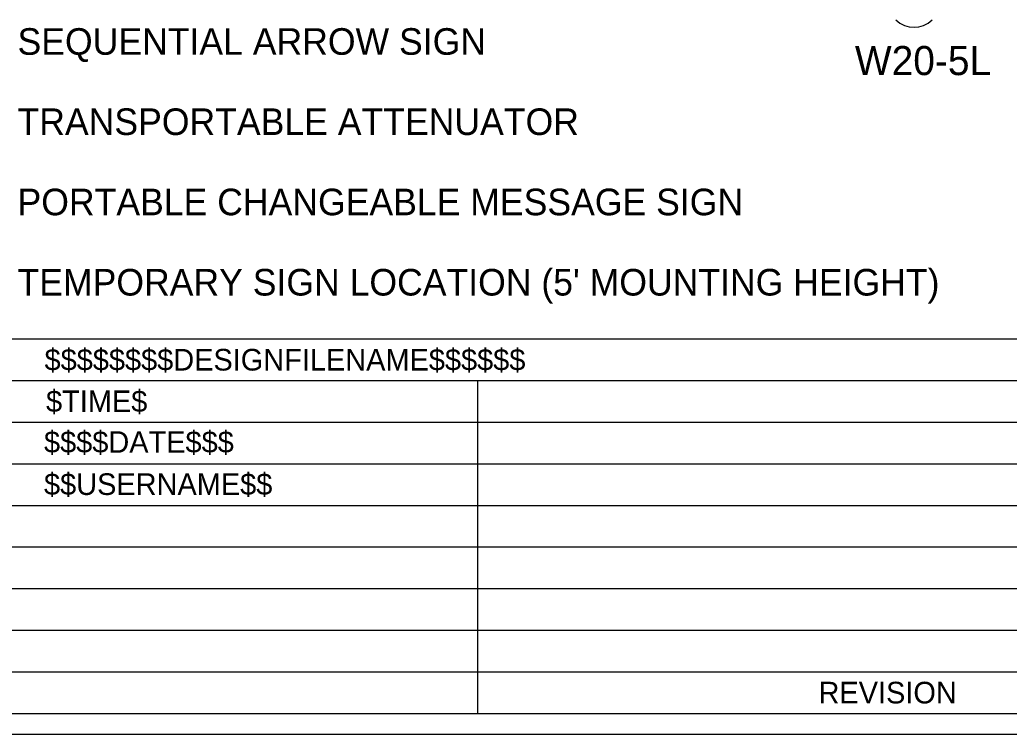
# Model space of a CAD drawing. Extents: x 99988 to 100172, y 99995 to 100047.
# Drawn here: x 100000.803 to 100003.778, y 99999.937 to 100002.085 of the extents above; entities that cross this region are included whole.
import ezdxf

# ---------------------------------------------------------------- set-up
doc = ezdxf.new("R2010")
doc.units = 0
for name, color, linetype in [('SH_DE_DetailBody1Text', 7, 'Continuous'), ('SH_GI_PlotLimits', 7, 'Continuous'), ('SH_GI_SheetBorder', 7, 'Continuous'), ('SH_GI_SheetTextInCells', 7, 'Continuous'), ('SH_GI_TitleBlockText', 7, 'Continuous'), ('TR_SN_WarningSigns', 7, 'Continuous')]:
    doc.layers.add(name, color=color, linetype=linetype)

msp = doc.modelspace()

# ---------------------------------------------------------------- linework, layer by layer
at = {"layer": 'SH_GI_PlotLimits'}
msp.add_lwpolyline([(99999.3125, 99999.9375), (100015.8125, 99999.9375), (100015.8125, 100010.4375), (99999.3125, 100010.4375)], close=True, dxfattribs=at)
at = {"layer": 'SH_GI_SheetBorder'}
for p, q in [((100000, 100001.1259), (100015.75, 100001.1259)), ((100000, 100001.0008), (100007.4566, 100001.0008)), ((100002.179, 100001.0008), (100002.179, 100000)), ((100000, 100000.8757), (100002.1821, 100000.8757)), ((100002.1821, 100000.8757), (100005.4466, 100000.8757)), ((100000, 100000.7506), (100002.1821, 100000.7506)), ((100002.1821, 100000.7506), (100005.4466, 100000.7506)), ((100000, 100000.6255), (100005.4466, 100000.6255)), ((100000, 100000.5004), (100005.4466, 100000.5004)), ((100000, 100000.3753), (100005.4466, 100000.3753)), ((100000, 100000.2502), (100005.4466, 100000.2502)), ((100000, 100000.1251), (100005.4466, 100000.1251)), ((100000, 100000), (100015.75, 100000))]:
    msp.add_line(p, q, dxfattribs=at)
at = {"layer": 'TR_SN_WarningSigns'}
msp.add_arc((100003.492, 100002.1397), 0.0769, 225, 314.9996, dxfattribs=at)

# ---------------------------------------------------------------- texts
at = {"layer": 'SH_DE_DetailBody1Text'}
for s, p in [('SEQUENTIAL ARROW SIGN', (100000.7962, 100001.9801)), ('TRANSPORTABLE ATTENUATOR', (100000.7962, 100001.7389)), ('PORTABLE CHANGEABLE MESSAGE SIGN', (100000.7962, 100001.4976)), ("TEMPORARY SIGN LOCATION (5' MOUNTING HEIGHT)", (100000.7962, 100001.2563))]:
    msp.add_text(s, height=0.08, dxfattribs=at).set_placement(p)
at = {"layer": 'SH_GI_SheetTextInCells'}
msp.add_text('REVISION', height=0.06505, dxfattribs=at).set_placement((100003.2048, 100000.03))
at = {"layer": 'SH_GI_TitleBlockText'}
for s, height, p in [('$$$$$$$$DESIGNFILENAME$$$$$$', 0.065052, (100000.8775, 100001.0308)), ('$TIME$', 0.06505, (100000.882, 100000.9059)), ('$$$$DATE$$$', 0.065052, (100000.8759, 100000.7835)), ('$$USERNAME$$', 0.065052, (100000.8759, 100000.6567))]:
    msp.add_text(s, height=height, dxfattribs=at).set_placement(p)
at = {"layer": 'TR_SN_WarningSigns'}
msp.add_text('W20-5L', height=0.0875, dxfattribs=at).set_placement((100003.3142, 100001.919))

doc.saveas('drawing.dxf')
